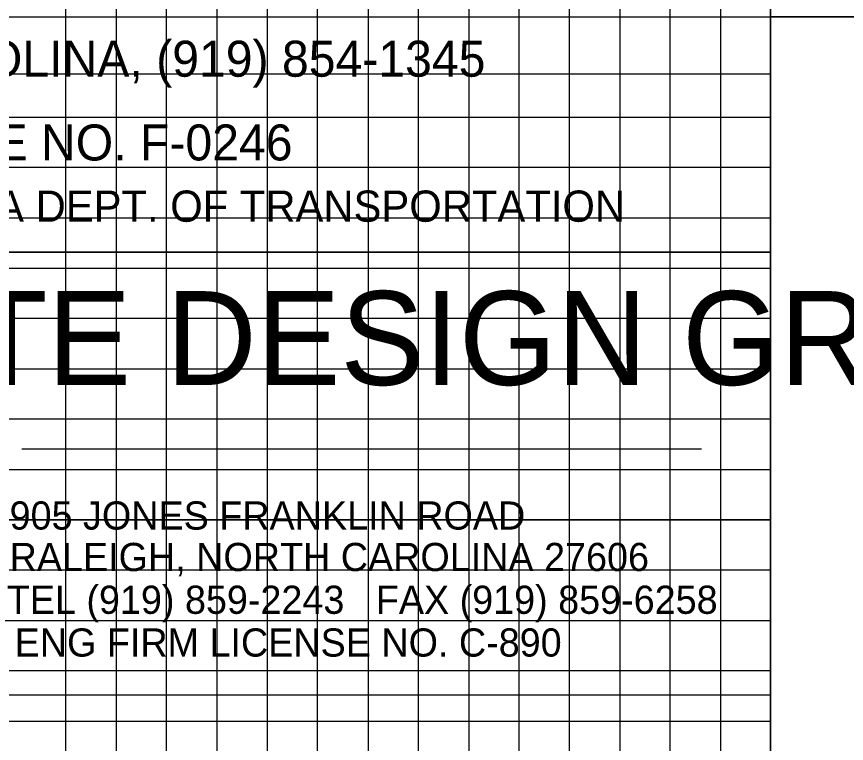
# Model space of a CAD drawing. Extents: x 2195312 to 2197200, y 76953 to 78053.
# Drawn here: x 2196703.8 to 2196786.2, y 77930.4 to 78002.6 of the extents above; entities that cross this region are included whole.
import ezdxf

# ---------------------------------------------------------------- set-up
doc = ezdxf.new("R2010")
doc.units = 0
for name, color, linetype in [('Exist Structure Minor Culvert Topo Terminator', 7, 'Continuous'), ('Old_Level_3', 7, 'Continuous'), ('Scratch_Level_0', 7, 'Continuous'), ('Sheet Cutting Line CELL', 7, 'Continuous'), ('Sheet Data Field CELL', 7, 'Continuous'), ('Sheet Plot Border Inside CELL', 7, 'Continuous'), ('Sheet Plot Border Outside CELL', 7, 'Continuous'), ('Sheet Sticker Preliminary CELL', 7, 'Continuous')]:
    doc.layers.add(name, color=color, linetype=linetype)

msp = doc.modelspace()

# ---------------------------------------------------------------- linework, layer by layer
at = {"layer": 'Exist Structure Minor Culvert Topo Terminator'}
for q in [(2196778.679, 78027.661), (2196644.279, 77979.233)]:
    msp.add_line((2196778.679, 77979.233), q, dxfattribs=at)
at = {"layer": 'Old_Level_3'}
msp.add_line((2196704.344, 77959.708), (2196771.848, 77959.708), dxfattribs=at)
for points in [[(2196644.279, 77979.233), (2196778.679, 77979.233), (2196778.679, 78027.661), (2196644.279, 78027.661)], [(2196644.279, 77979.233), (2196778.679, 77979.233), (2196778.679, 77935.22), (2196644.279, 77935.22)]]:
    msp.add_lwpolyline(points, close=True, dxfattribs=at)
for start, end in [(0, 180), (180, 0)]:
    msp.add_arc((2196735.118, 77944.818), 0.138, start, end, dxfattribs=at)
at = {"layer": 'Scratch_Level_0'}
msp.add_lwpolyline([(2195528.729, 77702.661), (2195528.729, 78027.661), (2196778.679, 78027.661), (2196778.679, 77866.611), (2196928.729, 77866.611), (2196928.729, 77702.661)], close=True, dxfattribs=at)
msp.add_lwpolyline([(2195528.729, 77702.661), (2195528.729, 78027.661), (2196778.679, 78027.661), (2196778.679, 77866.611), (2196928.729, 77866.611), (2196928.729, 77702.661)], close=True, dxfattribs=at)
at = {"layer": 'Sheet Cutting Line CELL'}
for points in [[(2196678.729, 77002.661), (2196678.729, 78027.661), (2196728.729, 78027.661), (2196728.729, 77002.661)], [(2196778.729, 77002.661), (2196778.729, 78027.661), (2196805.029, 78027.661)], [(2196778.679, 77952.661), (2195478.829, 77952.661), (2195478.829, 78002.611), (2196778.679, 78002.611)]]:
    msp.add_lwpolyline(points, dxfattribs=at)
at = {"layer": 'Sheet Data Field CELL'}
for points in [[(2196708.729, 77002.661), (2196708.729, 78027.661), (2196713.729, 78027.661), (2196713.729, 77002.661)], [(2196718.729, 77002.661), (2196718.729, 78027.661), (2196723.729, 78027.661), (2196723.729, 77002.661)], [(2196733.729, 77002.661), (2196733.729, 78027.661), (2196738.729, 78027.661), (2196738.729, 77002.661)], [(2196743.729, 77002.661), (2196743.729, 78027.661), (2196748.729, 78027.661), (2196748.729, 77002.661)], [(2196758.729, 77002.661), (2196758.729, 78027.661), (2196763.729, 78027.661), (2196763.729, 77002.661)], [(2196768.729, 77002.661), (2196768.729, 78027.661), (2196773.729, 78027.661), (2196773.729, 77002.661)], [(2196778.679, 77996.911), (2195529.729, 77996.911), (2195529.729, 77992.661), (2196778.679, 77992.661)], [(2196778.679, 77987.661), (2195528.729, 77987.661), (2195528.729, 77982.661), (2196778.679, 77982.661)], [(2196778.679, 77972.661), (2195528.729, 77972.661), (2195528.729, 77967.661), (2196778.679, 77967.661)], [(2196778.679, 77962.661), (2195528.729, 77962.661), (2195528.729, 77957.661), (2196778.679, 77957.661)], [(2196778.679, 77947.661), (2195528.729, 77947.661), (2195528.729, 77942.661), (2196778.679, 77942.661)], [(2196778.679, 77937.661), (2195528.729, 77937.661), (2195528.729, 77932.661), (2196778.679, 77932.661)]]:
    msp.add_lwpolyline(points, dxfattribs=at)
at = {"layer": 'Sheet Plot Border Inside CELL'}
for points in [[(2196778.679, 78027.661), (2196978.729, 78027.661), (2196978.729, 78002.611), (2196778.679, 78002.611)], [(2196778.679, 78002.611), (2196878.729, 78002.611), (2196878.729, 77890.111), (2196778.679, 77890.111)]]:
    msp.add_lwpolyline(points, close=True, dxfattribs=at)
at = {"layer": 'Sheet Plot Border Outside CELL'}
for points in [[(2196753.729, 77002.661), (2196753.729, 78027.661)], [(2195478.729, 77977.661), (2196778.679, 77977.661)]]:
    msp.add_lwpolyline(points, dxfattribs=at)
at = {"layer": 'Sheet Sticker Preliminary CELL'}
for p, q in [((2196728.729, 78027.661), (2196728.729, 77002.661)), ((2195478.729, 77952.661), (2196778.679, 77952.661))]:
    msp.add_line(p, q, dxfattribs=at)

# ---------------------------------------------------------------- texts
at = {"layer": 'Exist Structure Minor Culvert Topo Terminator'}
for s, height, rotation, p in [('RALEIGH,  NORTH CAROLINA, (919) 854-1345', 3.57538, 359.99996, (2196647.297, 77996.664)), ('NC LICENSE NO. F-0246', 3.57538, 359.99996, (2196676.236, 77988.343)), ('FOR NORTH CAROLINA DEPT. OF TRANSPORTATION', 3.10128, 359.99995, (2196657.573, 77982.256))]:
    msp.add_text(s, height=height, rotation=rotation, dxfattribs=at).set_placement(p)
at = {"layer": 'Old_Level_3'}
for s, height, p in [('SUNGATE DESIGN GROUP, P.A.', 9.31938, (2196654.972, 77966.044)), ('905 JONES FRANKLIN ROAD', 2.80071, (2196703.146, 77951.676)), ('RALEIGH, NORTH CAROLINA 27606', 2.80071, (2196703.146, 77947.554)), ('TEL (919) 859-2243   FAX (919) 859-6258', 2.80071, (2196702.862, 77943.307)), ('ENG FIRM LICENSE NO. C-890', 2.80071, (2196703.641, 77939.06))]:
    msp.add_text(s, height=height, dxfattribs=at).set_placement(p)

doc.saveas('drawing.dxf')
